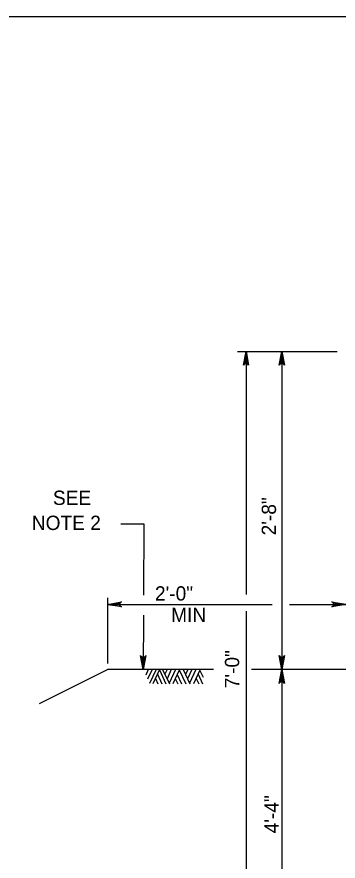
# Model space of a CAD drawing. Extents: x 632007860 to 635435983, y 295418622 to 297794622.
# Drawn here: x 632164486 to 632232951, y 295817961 to 295997622 of the extents above; entities that cross this region are included whole.
import ezdxf

# ---------------------------------------------------------------- set-up
doc = ezdxf.new("R2010")
doc.units = 0
for name, color, linetype in [('1', 7, 'Continuous'), ('S-DETL-DIMS', 7, 'Continuous'), ('S-DETL-T120', 7, 'Continuous'), ('S-GRND-MAJR', 7, 'Continuous')]:
    doc.layers.add(name, color=color, linetype=linetype)

msp = doc.modelspace()

# ---------------------------------------------------------------- linework, layer by layer
at = {"layer": '1'}
msp.add_lwpolyline([(632833860, 295433622), (632833860, 295997622), (632047860, 295997622), (632047860, 295433622), (632833860, 295433622), (632833860, 295459981), (632633860, 295459981), (632633860, 295524659), (632833860, 295524659), (632833860, 295553622), (632633860, 295553622), (632633860, 295433622), (632712661, 295433622), (632712661, 295459981), (632712661, 295433622), (632789661, 295433622), (632789661, 295459981), (632789661, 295447665), (632833860, 295447665)], dxfattribs=at)
at = {"layer": 'S-DETL-DIMS'}
for p, q in [((632232768, 295926343), (632211530, 295926343)), ((632213325, 295926439), (632213325, 295874668)), ((632220945, 295926439), (632220945, 295858743)), ((632186630, 295889724), (632191532, 295889724)), ((632191532, 295889724), (632191469, 295874563)), ((632183800, 295873994), (632183800, 295860027)), ((632183800, 295872602), (632218896, 295872602)), ((632213325, 295871180), (632213325, 295799017)), ((632222606, 295872602), (632234600, 295872602)), ((632191452, 295870302), (632191404, 295858743)), ((632220945, 295858743), (632220945, 295799017))]:
    msp.add_line(p, q, dxfattribs=at)
for points in [[(632213325, 295926439), (632213880, 295923480), (632213722, 295923708), (632213524, 295923825), (632213325, 295923859), (632213127, 295923825), (632212928, 295923708), (632212770, 295923480), (632213325, 295926439), (632212928, 295923708), (632213127, 295923825), (632213325, 295926439), (632213325, 295923859), (632213524, 295923825), (632213325, 295926439), (632213722, 295923708)], [(632220945, 295926439), (632221500, 295923480), (632221342, 295923708), (632221144, 295923825), (632220945, 295923859), (632220747, 295923825), (632220548, 295923708), (632220391, 295923480), (632220945, 295926439), (632220548, 295923708), (632220747, 295923825), (632220945, 295926439), (632220945, 295923859), (632221144, 295923825), (632220945, 295926439), (632221342, 295923708)], [(632183800, 295872602), (632186759, 295873157), (632186531, 295872999), (632186414, 295872800), (632186380, 295872602), (632186414, 295872403), (632186531, 295872205), (632186759, 295872047), (632183800, 295872602), (632186531, 295872205), (632186414, 295872403), (632183800, 295872602), (632186380, 295872602), (632186414, 295872800), (632183800, 295872602), (632186531, 295872999)], [(632234600, 295872602), (632231641, 295872047), (632231869, 295872205), (632231987, 295872403), (632232021, 295872602), (632231987, 295872800), (632231869, 295872999), (632231641, 295873157), (632234600, 295872602), (632231869, 295872999), (632231987, 295872800), (632234600, 295872602), (632232021, 295872602), (632231987, 295872403), (632234600, 295872602), (632231869, 295872205)], [(632191404, 295858743), (632190861, 295861705), (632190940, 295861590), (632191018, 295861476), (632191117, 295861417), (632191216, 295861358), (632191316, 295861340), (632191415, 295861323), (632191514, 295861339), (632191613, 295861356), (632191713, 295861414), (632191812, 295861473), (632191892, 295861586), (632191971, 295861700), (632191404, 295858743), (632191892, 295861586), (632191812, 295861473), (632191404, 295858743), (632191713, 295861414), (632191613, 295861356), (632191404, 295858743), (632191514, 295861339), (632191415, 295861323), (632191404, 295858743), (632191316, 295861340), (632191216, 295861358), (632191404, 295858743), (632191117, 295861417), (632191018, 295861476), (632191404, 295858743), (632190940, 295861590)], [(632220945, 295858743), (632220391, 295861702), (632220548, 295861474), (632220747, 295861357), (632220945, 295861323), (632221144, 295861357), (632221342, 295861474), (632221500, 295861702), (632220945, 295858743), (632221342, 295861474), (632221144, 295861357), (632220945, 295858743), (632220945, 295861323), (632220747, 295861357), (632220945, 295858743), (632220548, 295861474)], [(632220945, 295858743), (632221500, 295855784), (632221342, 295856012), (632221144, 295856129), (632220945, 295856163), (632220747, 295856129), (632220548, 295856012), (632220391, 295855784), (632220945, 295858743), (632220548, 295856012), (632220747, 295856129), (632220945, 295858743), (632220945, 295856163), (632221144, 295856129), (632220945, 295858743), (632221342, 295856012)]]:
    msp.add_lwpolyline(points, dxfattribs=at)
at = {"layer": 'S-GRND-MAJR'}
for p, q in [((632169312, 295851474), (632183800, 295858743)), ((632206409, 295858743), (632183800, 295858743)), ((632192491, 295858746), (632191938, 295857535)), ((632193301, 295858746), (632192348, 295856657)), ((632194141, 295858746), (632192768, 295855770)), ((632194904, 295858747), (632193483, 295855665)), ((632194856, 295858651), (632196240, 295855675)), ((632195552, 295858747), (632196993, 295855676)), ((632196506, 295858747), (632196039, 295857717)), ((632197403, 295858747), (632196487, 295856753)), ((632198280, 295858747), (632196926, 295855828)), ((632199129, 295858747), (632197708, 295855676)), ((632199091, 295858661), (632200475, 295855676)), ((632199930, 295858747), (632201362, 295855676)), ((632200913, 295858747), (632200427, 295857689)), ((632201781, 295858748), (632200856, 295856754)), ((632202658, 295858748), (632201295, 295855819)), ((632203574, 295858748), (632202153, 295855676)), ((632203488, 295858557), (632204166, 295857107)), ((632308142, 295858743), (632214495, 295858743)), ((632194017, 295856839), (632194551, 295855675)), ((632194446, 295857764), (632195410, 295855675)), ((632198252, 295856811), (632198767, 295855676)), ((632198652, 295857707), (632199587, 295855676)), ((632202697, 295856850), (632203231, 295855677)), ((632203107, 295857737), (632204070, 295855677))]:
    msp.add_line(p, q, dxfattribs=at)

# ---------------------------------------------------------------- texts
at = {"layer": 'S-DETL-T120'}
for s, p in [('SEE ', (632172167, 295893758)), ('NOTE 2', (632167667, 295888424)), ('2\'-0"', (632193918, 295873403)), ('MIN', (632197362, 295868831))]:
    msp.add_text(s, height=3048.1, dxfattribs=at).set_placement(p)
for s, p in [('2\'-8"', (632219713, 295887279)), ('7\'-0"', (632211867, 295854741)), ('4\'-4"', (632220303, 295823870))]:
    msp.add_text(s, height=3048, rotation=90, dxfattribs=at).set_placement(p)

doc.saveas('drawing.dxf')
